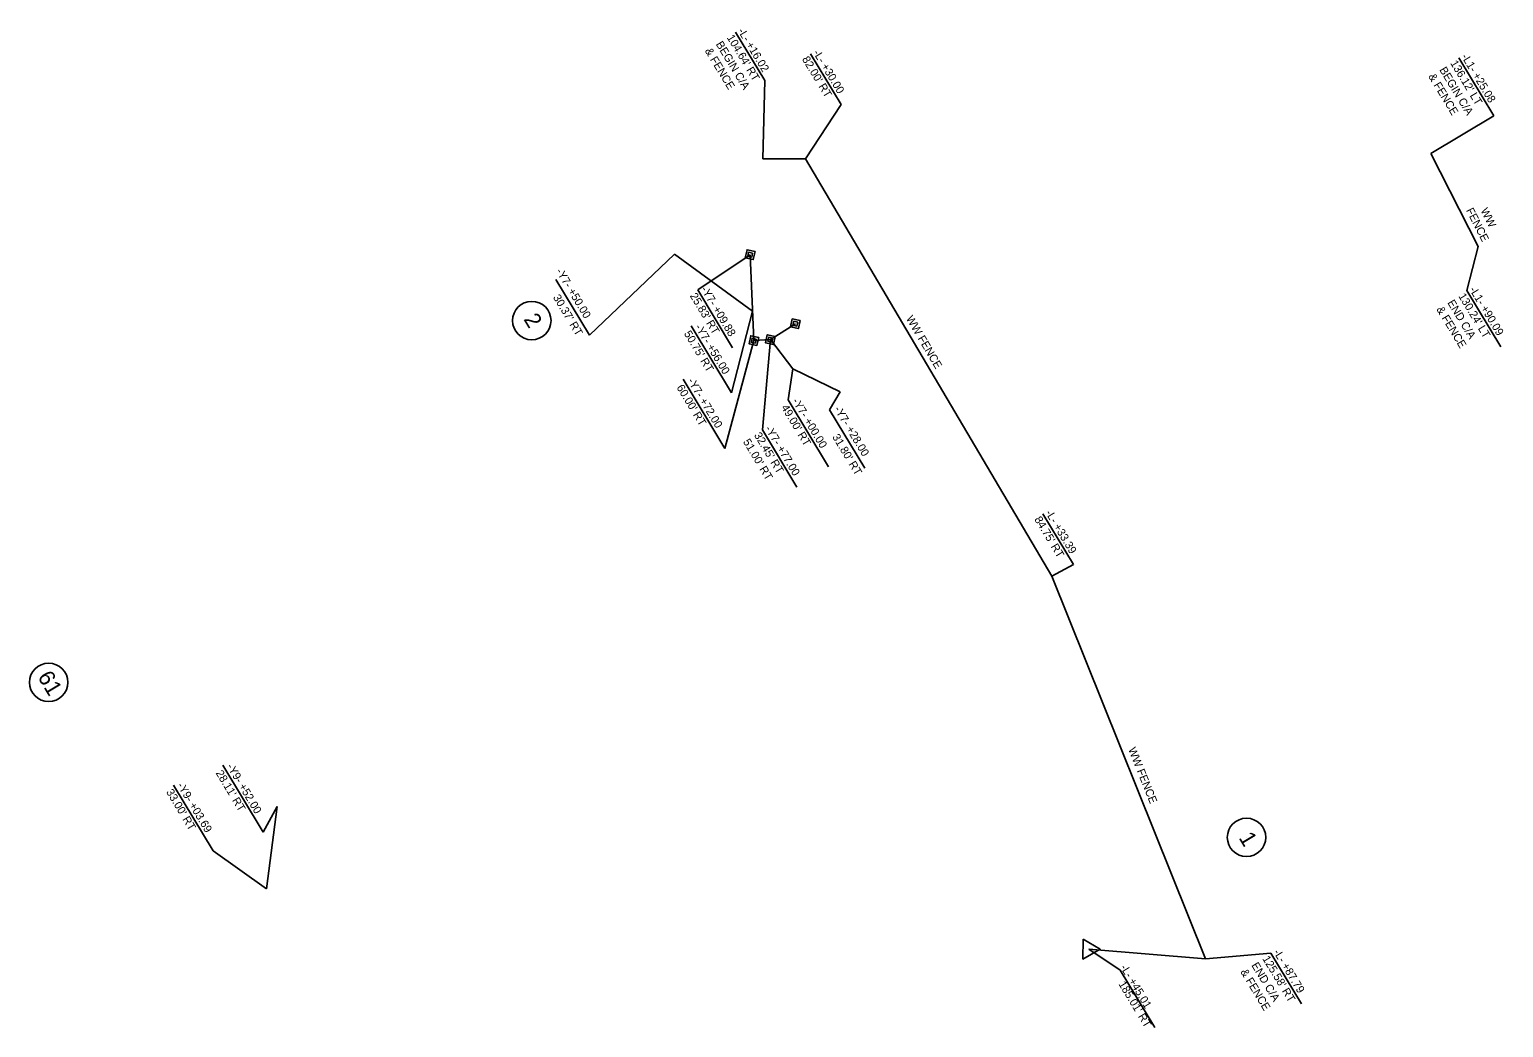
# Model space of a CAD drawing. Extents: x 1779796 to 1783527, y 810952 to 815815.
# Drawn here: x 1779796 to 1780717, y 815192 to 815815 of the extents above; entities that cross this region are included whole.
import ezdxf

# ---------------------------------------------------------------- set-up
doc = ezdxf.new("R2010")
doc.units = 0
for name, color, linetype in [('Prop Dimension Text', 7, 'Continuous'), ('Prop Easement Construction', 7, 'Continuous'), ('Prop Easement Construction Station Offsets', 7, 'Continuous'), ('Prop Easement Permanent Utility', 7, 'Continuous'), ('Prop Easement Permanent Utility Station Offsets', 7, 'Continuous'), ('Prop Fence Woven Wire', 7, 'Continuous'), ('Prop Parcel Number CELL', 7, 'Continuous'), ('Prop Parcel Number Text', 7, 'Continuous'), ('Prop ROW CA Lines', 7, 'Continuous'), ('Prop ROW Marker CELL', 7, 'Continuous'), ('Prop ROW Permanent Easement CELL', 7, 'Continuous'), ('Prop ROW RW Lines', 7, 'Continuous'), ('Prop ROW Station Offsets', 7, 'Continuous')]:
    doc.layers.add(name, color=color, linetype=linetype)

msp = doc.modelspace()

# ---------------------------------------------------------------- linework, layer by layer
at = {"layer": 'Prop Easement Construction'}
for p, q in [((1780198.97, 815674.94), (1780247.84, 815639.34)), ((1780258.91, 815621.49), (1780272.95, 815603.16)), ((1780272.95, 815603.16), (1780302.49, 815588.78)), ((1779950.78, 815329.83), (1779944.23, 815278.33))]:
    msp.add_line(p, q, dxfattribs=at)
at = {"layer": 'Prop Easement Construction Station Offsets'}
for p, q in [((1780198.97, 815674.94), (1780145.95, 815624.31)), ((1780124.94, 815659.11), (1780145.95, 815624.31)), ((1780234.57, 815588.29), (1780209.41, 815630.16)), ((1780272.95, 815603.16), (1780270.15, 815583.97)), ((1780295.32, 815542.1), (1780270.15, 815583.97)), ((1780302.49, 815588.78), (1780295.91, 815577.69)), ((1780295.91, 815577.69), (1780317.98, 815541.12)), ((1779942.08, 815313.71), (1779916.92, 815355.59)), ((1779910.85, 815302), (1779886.11, 815343.18)), ((1779942.08, 815313.71), (1779950.78, 815329.83)), ((1779910.85, 815302), (1779944.23, 815278.33))]:
    msp.add_line(p, q, dxfattribs=at)
msp.add_lwpolyline([(1780234.57, 815588.29), (1780247.84, 815639.34)], dxfattribs=at)
at = {"layer": 'Prop Easement Permanent Utility'}
for p, q in [((1780246.32, 815674.58), (1780248.63, 815620.87)), ((1780258.91, 815621.49), (1780274.56, 815631.45)), ((1780248.63, 815620.87), (1780258.91, 815621.49))]:
    msp.add_line(p, q, dxfattribs=at)
at = {"layer": 'Prop Easement Permanent Utility Station Offsets'}
for p, q in [((1780235.31, 815616.4), (1780213.55, 815652.62)), ((1780230.51, 815553.48), (1780204.52, 815596.75)), ((1780275.56, 815529.41), (1780254.07, 815565.19))]:
    msp.add_line(p, q, dxfattribs=at)
for points in [[(1780213.55, 815652.62), (1780246.32, 815674.58)], [(1780230.51, 815553.48), (1780248.63, 815620.87)], [(1780254.07, 815565.19), (1780258.91, 815621.49)]]:
    msp.add_lwpolyline(points, dxfattribs=at)
at = {"layer": 'Prop Fence Woven Wire'}
for p, q in [((1780254.21, 815734.55), (1780280.78, 815734.48)), ((1780280.78, 815734.48), (1780434.79, 815473.69)), ((1780671.43, 815737.88), (1780701.12, 815679.74)), ((1780434.79, 815473.69), (1780530.81, 815234.59))]:
    msp.add_line(p, q, dxfattribs=at)
at = {"layer": 'Prop Parcel Number CELL'}
for p, q in [((1780109.9, 815633.42), (1780109.9, 815633.42)), ((1779808.13, 815407.34), (1779808.13, 815407.34)), ((1780556.36, 815310.47), (1780556.36, 815310.47))]:
    msp.add_line(p, q, dxfattribs=at)
for centre in [(1780109.9, 815633.42), (1779808.13, 815407.34), (1780556.36, 815310.47)]:
    msp.add_circle(centre, 12, dxfattribs=at)
at = {"layer": 'Prop ROW CA Lines'}
for p, q in [((1780254.21, 815734.55), (1780280.78, 815734.48)), ((1780280.78, 815734.48), (1780434.79, 815473.69)), ((1780671.43, 815737.88), (1780701.12, 815679.74)), ((1780434.79, 815473.69), (1780530.81, 815234.59))]:
    msp.add_line(p, q, dxfattribs=at)
at = {"layer": 'Prop ROW Marker CELL'}
for p, q in [((1780246.32, 815674.58), (1780246.32, 815674.58)), ((1780274.56, 815631.45), (1780274.56, 815631.45)), ((1780248.63, 815620.87), (1780248.63, 815620.87)), ((1780258.91, 815621.49), (1780258.91, 815621.49)), ((1780457.84, 815240.66), (1780457.84, 815240.66))]:
    msp.add_line(p, q, dxfattribs=at)
msp.add_lwpolyline([(1780454.27, 815246.92), (1780465.04, 815240.62), (1780454.21, 815234.42)], close=True, dxfattribs=at)
at = {"layer": 'Prop ROW Permanent Easement CELL'}
for points in [[(1780249.36, 815676.52), (1780248.25, 815671.55), (1780243.29, 815672.65), (1780244.39, 815677.62)], [(1780247.84, 815675.55), (1780247.29, 815673.06), (1780244.8, 815673.62), (1780245.35, 815676.1)], [(1780277.59, 815633.39), (1780276.49, 815628.42), (1780271.52, 815629.52), (1780272.62, 815634.49)], [(1780276.08, 815632.42), (1780275.52, 815629.94), (1780273.04, 815630.49), (1780273.59, 815632.97)], [(1780251.67, 815622.81), (1780250.56, 815617.84), (1780245.59, 815618.94), (1780246.7, 815623.91)], [(1780250.15, 815621.84), (1780249.6, 815619.36), (1780247.11, 815619.91), (1780247.66, 815622.39)], [(1780261.94, 815623.42), (1780260.84, 815618.45), (1780255.87, 815619.56), (1780256.97, 815624.53)], [(1780260.43, 815622.46), (1780259.87, 815619.97), (1780257.39, 815620.52), (1780257.94, 815623.01)]]:
    msp.add_lwpolyline(points, close=True, dxfattribs=at)
at = {"layer": 'Prop ROW RW Lines'}
msp.add_line((1780457.84, 815240.66), (1780530.81, 815234.59), dxfattribs=at)
at = {"layer": 'Prop ROW Station Offsets'}
for p, q in [((1780255.38, 815783.36), (1780237.09, 815813.66)), ((1780303.18, 815768.48), (1780284.07, 815800.14)), ((1780710.95, 815761.31), (1780689.02, 815797.64)), ((1780710.95, 815761.31), (1780671.43, 815737.88)), ((1780694.06, 815652.1), (1780701.12, 815679.74)), ((1780715.24, 815617.02), (1780694.06, 815652.1)), ((1780448.24, 815481.05), (1780429.2, 815512.6)), ((1780590.68, 815206.54), (1780571.63, 815238.09)), ((1780499.02, 815191.66), (1780477.37, 815227.53))]:
    msp.add_line(p, q, dxfattribs=at)
for points in [[(1780255.38, 815783.36), (1780254.21, 815734.55)], [(1780303.18, 815768.48), (1780280.78, 815734.48)], [(1780448.24, 815481.05), (1780434.79, 815473.69)], [(1780477.37, 815227.53), (1780457.84, 815240.66)], [(1780571.63, 815238.09), (1780530.81, 815234.59)]]:
    msp.add_lwpolyline(points, dxfattribs=at)

# ---------------------------------------------------------------- texts
at = {"layer": 'Prop Dimension Text'}
for s, rotation, p in [('FENCE', 296.84876, (1780693.38, 815702.36)), ('WW', 296.84876, (1780702.39, 815702.27)), ('WW FENCE', 300.31972, (1780343.49, 815634.81)), ('WW FENCE', 291.87056, (1780482.35, 815365.55))]:
    msp.add_text(s, height=5, rotation=rotation, dxfattribs=at).set_placement(p)
at = {"layer": 'Prop Easement Construction Station Offsets'}
for s, rotation, p in [('-Y7- +50.00', 301.11542, (1780124.76, 815664.26)), ("30.37' RT", 301.11542, (1780122.93, 815647.93)), ('-Y7- +56.00', 301, (1780211.62, 815629.4)), ("50.75' RT", 301, (1780204.76, 815625.28)), ('-Y7- +00.00', 301, (1780272.36, 815583.21)), ("49.00' RT", 301, (1780265.51, 815579.09)), ('-Y7- +28.00', 301.11542, (1780298.58, 815578.11)), ("31.80' RT", 301.11542, (1780297.37, 815560.76)), ('-Y9- +52.00', 301, (1779919.13, 815354.82)), ('-Y9- +03.69', 301, (1779888.15, 815343.01)), ("28.11' RT", 301, (1779912.27, 815350.7)), ("33.00' RT", 301, (1779881.29, 815338.89))]:
    msp.add_text(s, height=5, rotation=rotation, dxfattribs=at).set_placement(p)
at = {"layer": 'Prop Easement Permanent Utility Station Offsets'}
for s, p in [("25.83' RT", (1780208.44, 815648.91)), ('-Y7- +09.88', (1780215.3, 815653.03)), ("60.00' RT", (1780200.16, 815591.62)), ('-Y7- +72.00', (1780207.02, 815595.74)), ('-Y7- +77.00', (1780255.36, 815565.94)), ("51.00' RT", (1780241.65, 815557.7)), ("32.45' RT", (1780248.51, 815561.82))]:
    msp.add_text(s, height=5, rotation=301, dxfattribs=at).set_placement(p)
at = {"layer": 'Prop Parcel Number Text'}
for s, p in [('2', (1780104.53, 815634.26)), ('61', (1779800.92, 815410.79)), ('1', (1780551.26, 815310.24))]:
    msp.add_text(s, height=10, rotation=301, dxfattribs=at).set_placement(p)
at = {"layer": 'Prop ROW Station Offsets'}
for s, p in [('-L- +16.02', (1780238.38, 815814.42)), ('BEGIN C/A', (1780224.68, 815806.15)), ("104.64' RT", (1780231.53, 815810.29)), ('& FENCE', (1780217.83, 815802.02)), ("82.00' RT", (1780278.51, 815796.77)), ('-L- +30.00', (1780285.36, 815800.9)), ("136.12' LT", (1780683.47, 815794.27)), ('-L1- +25.08', (1780690.32, 815798.4)), ('& FENCE', (1780669.77, 815786)), ('BEGIN C/A', (1780676.62, 815790.13)), ("130.24' LT", (1780688.51, 815648.73)), ('-L1- +90.09', (1780695.36, 815652.86)), ('& FENCE', (1780674.81, 815640.46)), ('END C/A ', (1780681.66, 815644.59)), ("84.75' RT", (1780423.64, 815509.23)), ('-L- +33.39', (1780430.49, 815513.36)), ("125.58' RT", (1780566.08, 815234.71)), ('-L- +87.79', (1780572.93, 815238.85)), ('  -L- +45.01', (1780475.38, 815232.48)), ('& FENCE', (1780552.38, 815226.45)), ('END C/A', (1780559.23, 815230.58)), ("185.01' RT", (1780476.21, 815218.85))]:
    msp.add_text(s, height=5, rotation=301.11542, dxfattribs=at).set_placement(p)

doc.saveas('drawing.dxf')
